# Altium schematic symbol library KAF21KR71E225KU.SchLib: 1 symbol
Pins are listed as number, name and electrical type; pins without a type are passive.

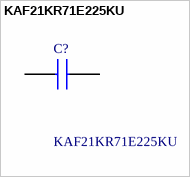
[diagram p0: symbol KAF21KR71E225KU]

## KAF21KR71E225KU
designator C?
Multilayer Ceramic Capacitors MLCC - SMD/SMT 25V 2.2uF X7R 0805 10% AEC-Q200 FLEXITERM; Manufacturer_Name: Kyocera AVX; Geometry.Height: 1.4mm
footprint CAPC2012X140N
pins: 1, 2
